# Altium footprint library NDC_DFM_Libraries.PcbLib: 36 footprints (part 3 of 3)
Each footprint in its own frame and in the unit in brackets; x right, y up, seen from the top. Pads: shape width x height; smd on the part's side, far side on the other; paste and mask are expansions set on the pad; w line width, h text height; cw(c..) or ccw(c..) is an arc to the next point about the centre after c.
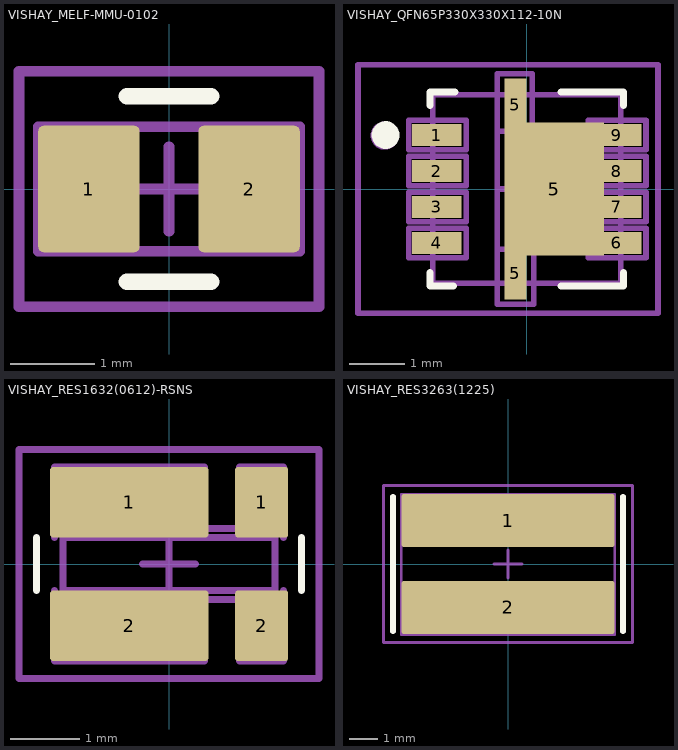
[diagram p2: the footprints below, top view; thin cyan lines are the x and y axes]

## VISHAY_MELF-MMU-0102 [mm]
pads (2):
  rrect10% 1.2x1.5 smd: 1(-0.95,0) 2(0.95,0)
Top Overlay:
  lines w0.2: -0.5,-1.1 0.5,-1.1 ; -0.5,1.1 0.5,1.1
M06 - ASSY TOP:
  lines w0.127: -1.549,-0.737 -1.549,0.737 1.549,0.737 1.549,-0.737 -1.549,-0.737
  text ".designator" at -1.219,-0.432 h0.89
M15 - COURTYARD TOP:
  lines w0.127: -0.5,0 0.5,0 ; 0,-0.5 0,0.5 ; -1.778,-1.397 1.778,-1.397 1.778,1.397 -1.778,1.397 -1.778,-1.397
3D body: height 1.1, standoff 0, extent -1,-0.55 1,0.55

## VISHAY_QFN65P330X330X112-10N [mm] "QFN, 10-Leads, Body 3.4x3.4mm (max), Pitch 0.65mm, IPC Medium Density"
height 1.12
pads (11):
  rect 0.9x0.4 smd mask+0: 1(-1.625,0.975) 2(-1.625,0.325) 3(-1.625,-0.325) 4(-1.625,-0.975) 6(1.625,-0.975) 7(1.625,-0.325) 8(1.625,0.325) 9(1.625,0.975)
  rect 0.4x0.95 smd: 5(-0.203,-1.524) 5(-0.203,1.524)
  rect 1.8x2.4 smd: 5(0.5,0)
Top Overlay:
  circle w0.25: c-2.55,0.975 r0.125
  lines w0.127: -1.75,-1.513 -1.75,-1.75 -1.321,-1.75 ; -1.75,1.513 -1.75,1.75 -1.295,1.75 ; 0.625,-1.75 1.75,-1.75 1.75,-1.513 ; 0.625,1.75 1.75,1.75 1.75,1.513
M06 - ASSY TOP:
  circle w0.254: c-2.565,0.965 r0.127
  lines w0.1: -0.533,1.069 -0.533,2.083 0.102,2.083 0.102,1.069 ; 0.127,-1.092 0.127,-2.083 -0.533,-2.083 -0.533,-1.092 ; 1.116,-1.092 -0.533,-1.092 ; 1.118,1.041 -0.533,1.041 -0.533,-1.092 ; -2.134,-1.239 -1.092,-1.239 -1.092,-0.705 -2.134,-0.705 -2.134,-1.239 ; -2.134,-0.589 -1.092,-0.589 -1.092,-0.055 -2.134,-0.055 -2.134,-0.589 ; -2.134,0.061 -1.092,0.061 -1.092,0.595 -2.134,0.595 -2.134,0.061 ; -2.134,0.711 -2.134,1.245 -1.092,1.245 -1.092,0.711 -2.134,0.711 ; -1.7,-1.7 -1.7,1.7 1.7,1.7 1.7,-1.7 -1.7,-1.7 ; 1.116,-1.239 2.158,-1.239 2.158,-0.705 1.116,-0.705 1.116,-1.239 ; 1.116,-0.589 2.158,-0.589 2.158,-0.055 1.116,-0.055 1.116,-0.589 ; 1.116,0.061 2.158,0.061 2.158,0.595 1.116,0.595 1.116,0.061 ; 1.116,0.711 2.158,0.711 2.158,1.245 1.116,1.245 1.116,0.711
  text ".Designator" at -2.286,-3.277 h0.89
M15 - COURTYARD TOP:
  lines w0.1: -0.5,0 0.5,0 ; 0,-0.5 0,0.5 ; -3.048,-2.25 -3.048,2.25 2.375,2.25 2.375,-2.25 -3.048,-2.25
3D body: height 1.13, standoff 0.01, extent -1.626,-1.7 1.644,1.7

## VISHAY_RES1632(0612)-RSNS [mil] "4-Terminal, 1W, Current-sense Resistor"
height 15
pads (4):
  rrect10% 90x40 smd: 1(-22.5,35) 2(-22.5,-35)
  rrect10% 30x40 smd: 1(52.5,35) 2(52.5,-35)
Top Overlay:
  lines w3.94: -75,-15 -75,15 ; 75,-15 75,15
M06 - ASSY TOP:
  lines w3.94: -65,-15 -65,-55 20,-55 20,-35 ; -65,15 -65,55 20,55 20,35 ; -60,-15 60,-15 ; -60,15 60,15 ; 40,-35 40,-55 65,-55 65,-15 ; 40,35 40,55 65,55 65,15 ; -60,-30 20,-30 20,-20 40,-20 40,-30 60,-30 60,30 40,30 40,20 20,20 20,30 -60,30 -60,-30
  text ".designator" at -76,-109 h35
M15 - COURTYARD TOP:
  lines w3.94: -15,0 15,0 ; 0,-15 0,15 ; -85,-65 85,-65 85,65 -85,65 -85,-65
3D body: height 14.5, standoff 0.5, extent -60,-15 60,15
3D body: height 15, standoff 0, extent -60,-30 60,-15
3D body: height 15, standoff 0, extent -60,15 60,30

## VISHAY_RES3263(1225) [mm] "Long Side Termination Thick Film Chip Resistor, 2W"
height 0.75
pads (2):
  rrect10% 7.6x1.9 smd: 1(0,1.55) 2(0,-1.55)
Top Overlay:
  lines w0.2: -4.1,-2.4 -4.1,2.4 ; 4.1,-2.4 4.1,2.4
M06 - ASSY TOP:
  lines w0.1: -3.81,-2.515 3.81,-2.515 3.81,2.489 -3.81,2.489 -3.81,-2.515
  text ".designator" at -3.404,-0.279 h0.89
M15 - COURTYARD TOP:
  lines w0.1: -0.5,0 0.5,0 ; 0,-0.5 0,0.5 ; -4.445,-2.8 -4.445,2.8 4.445,2.8 4.445,-2.8 -4.445,-2.8
3D body: height 0.63, standoff 0.01, extent -3.15,-1.55 3.15,1.55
